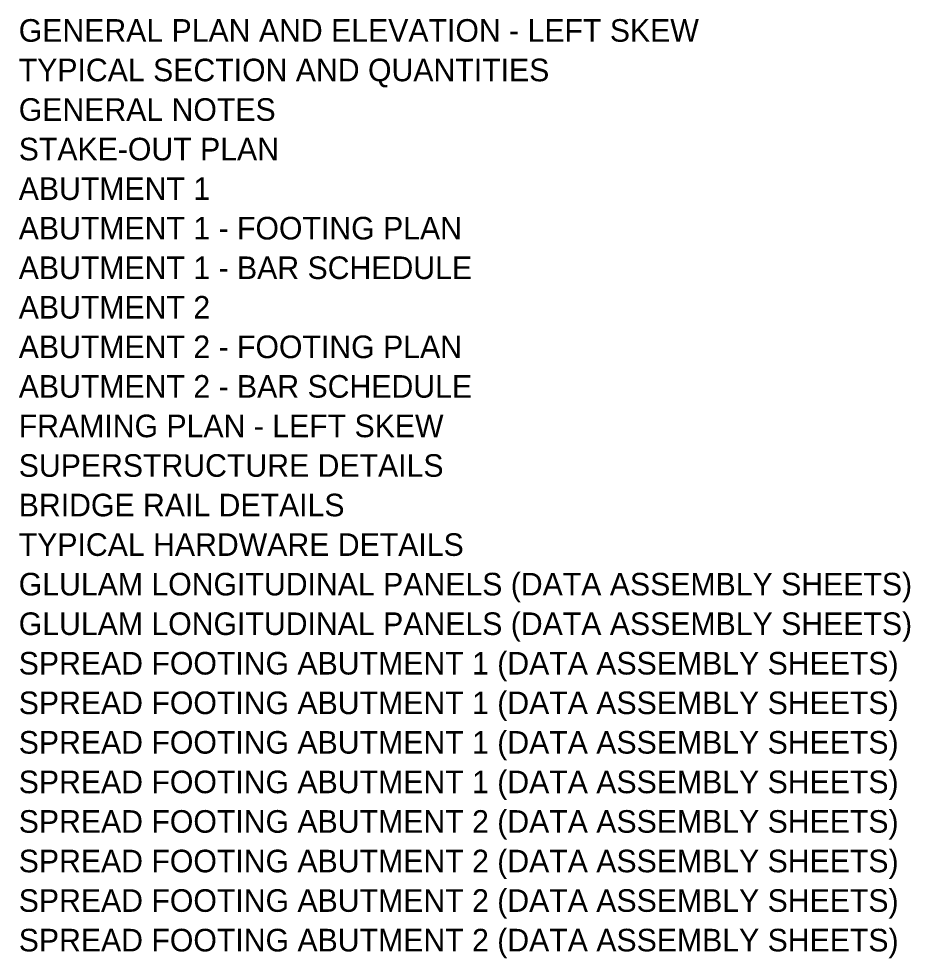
# Model space of a CAD drawing. Extents: x -762 to 6536, y -6882 to 0.
# Drawn here: x 2716 to 5490, y -6882 to -3959 of the extents above; entities that cross this region are included whole.
import ezdxf

# ---------------------------------------------------------------- set-up
doc = ezdxf.new("R2010")
doc.units = 0
doc.layers.add('62', color=7, linetype='Continuous')

msp = doc.modelspace()

# ---------------------------------------------------------------- texts
at = {"layer": '62'}
for s, height, p in [('GENERAL PLAN AND ELEVATION - LEFT SKEW', 70.313, (2715.9, -4030.4)), ('TYPICAL SECTION AND QUANTITIES', 70.313, (2715.9, -4153.4)), ('GENERAL NOTES', 70.313, (2715.9, -4276.5)), ('STAKE-OUT PLAN', 70.313, (2715.9, -4399.5)), ('ABUTMENT 1', 70.31, (2715.9, -4522.6)), ('ABUTMENT 1 - FOOTING PLAN', 70.313, (2715.9, -4645.6)), ('ABUTMENT 1 - BAR SCHEDULE', 70.313, (2715.9, -4768.7)), ('ABUTMENT 2', 70.31, (2715.9, -4891.7)), ('ABUTMENT 2 - FOOTING PLAN', 70.313, (2715.9, -5014.7)), ('ABUTMENT 2 - BAR SCHEDULE', 70.313, (2715.9, -5137.8)), ('FRAMING PLAN - LEFT SKEW', 70.313, (2715.9, -5260.8)), ('SUPERSTRUCTURE DETAILS', 70.313, (2715.9, -5383.9)), ('BRIDGE RAIL DETAILS', 70.313, (2715.9, -5506.9)), ('TYPICAL HARDWARE DETAILS', 70.313, (2715.9, -5630)), ('GLULAM LONGITUDINAL PANELS (DATA ASSEMBLY SHEETS)', 70.313, (2715.9, -5753)), ('GLULAM LONGITUDINAL PANELS (DATA ASSEMBLY SHEETS)', 70.313, (2715.9, -5876.1)), ('SPREAD FOOTING ABUTMENT 1 (DATA ASSEMBLY SHEETS)', 70.313, (2715.9, -5999.1)), ('SPREAD FOOTING ABUTMENT 1 (DATA ASSEMBLY SHEETS)', 70.313, (2715.9, -6122.2)), ('SPREAD FOOTING ABUTMENT 1 (DATA ASSEMBLY SHEETS)', 70.313, (2715.9, -6245.2)), ('SPREAD FOOTING ABUTMENT 1 (DATA ASSEMBLY SHEETS)', 70.313, (2715.9, -6368.3)), ('SPREAD FOOTING ABUTMENT 2 (DATA ASSEMBLY SHEETS)', 70.313, (2715.9, -6491.3)), ('SPREAD FOOTING ABUTMENT 2 (DATA ASSEMBLY SHEETS)', 70.313, (2715.9, -6614.4)), ('SPREAD FOOTING ABUTMENT 2 (DATA ASSEMBLY SHEETS)', 70.313, (2715.9, -6737.4)), ('SPREAD FOOTING ABUTMENT 2 (DATA ASSEMBLY SHEETS)', 70.313, (2715.9, -6860.5))]:
    msp.add_text(s, height=height, dxfattribs=at).set_placement(p)

doc.saveas('drawing.dxf')
